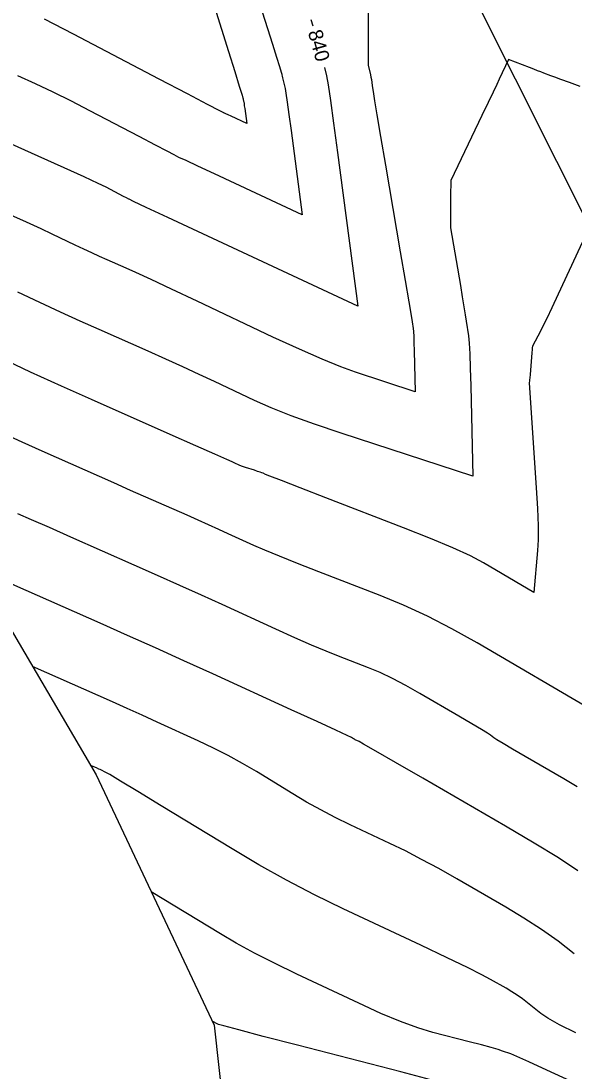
# Model space of a CAD drawing. Extents: x 1715724 to 1716561, y 394063 to 395906.
# Drawn here: x 1716345.4 to 1716399.3, y 394300.9 to 394403.2 of the extents above; entities that cross this region are included whole.
import ezdxf

# ---------------------------------------------------------------- set-up
doc = ezdxf.new("R2010")
doc.units = 0
for name, color, linetype in [('DT_X_Contour_Major', 7, 'Continuous'), ('DT_X_Contour_Minor', 7, 'Continuous'), ('DT_X_TIN_Hull', 7, 'Continuous'), ('GE_P_CL_10', 7, 'Continuous')]:
    doc.layers.add(name, color=color, linetype=linetype)

msp = doc.modelspace()

# ---------------------------------------------------------------- linework, layer by layer
at = {"layer": 'DT_X_Contour_Major'}
for points in [[(1716373.61, 394403.29), (1716373.81, 394402.67)], [(1716374.94, 394398.63), (1716375.13, 394397.81), (1716375.29, 394396.94), (1716375.52, 394395.41), (1716375.83, 394393.21), (1716376.22, 394390.33), (1716378.18, 394375.37), (1716359.66, 394384.02), (1716357.57, 394385), (1716356.32, 394385.58), (1716355.9, 394385.78), (1716355.89, 394385.78), (1716355.65, 394385.91), (1716355.35, 394386.06), (1716354.94, 394386.28), (1716353.66, 394386.95), (1716352.89, 394387.33), (1716351.53, 394387.96), (1716349.59, 394388.85), (1716347.05, 394389.99), (1716339.51, 394393.37)], [(1716399.56, 394328.56), (1716398.27, 394329.33), (1716394.51, 394331.49), (1716393.27, 394332.22), (1716392.34, 394332.76), (1716391.74, 394333.13), (1716391.45, 394333.31), (1716391.13, 394333.57), (1716390.84, 394333.76), (1716390.23, 394334.13), (1716389.29, 394334.69), (1716388.03, 394335.43), (1716384.24, 394337.65), (1716382.86, 394338.43), (1716381.56, 394339.11), (1716380.35, 394339.68), (1716379.22, 394340.15), (1716376.31, 394341.27), (1716375.11, 394341.75), (1716373.69, 394342.35), (1716372.06, 394343.07), (1716370.2, 394343.91), (1716364.96, 394346.31), (1716362.95, 394347.22), (1716360.86, 394348.16), (1716358.68, 394349.14), (1716356.41, 394350.14), (1716350.24, 394352.87), (1716348.13, 394353.8), (1716346.4, 394354.56), (1716345.06, 394355.15)], [(1716388.29, 394299.2), (1716385.79, 394299.87), (1716382.38, 394300.77), (1716372.3, 394303.38), (1716368.98, 394304.24), (1716366.59, 394304.87), (1716365.13, 394305.25), (1716364.6, 394305.4), (1716364.42, 394305.49), (1716364.35, 394305.52), (1716364.3, 394305.55), (1716364.24, 394305.58), (1716363.99, 394305.73)]]:
    msp.add_lwpolyline(points, dxfattribs=at)
at = {"layer": 'DT_X_Contour_Minor'}
for points in [[(1716363.69, 394406.22), (1716365.58, 394400.19), (1716366.2, 394398.22), (1716366.64, 394396.8), (1716366.91, 394395.94), (1716367, 394395.65), (1716367, 394395.62), (1716367.01, 394395.6), (1716367.01, 394395.57), (1716367.02, 394395.54), (1716367.03, 394395.49), (1716367.06, 394395.35), (1716367.08, 394395.27), (1716367.1, 394395.12), (1716367.13, 394394.9), (1716367.17, 394394.62), (1716367.36, 394393.16), (1716365.84, 394393.87), (1716365.55, 394394.01), (1716365.34, 394394.1), (1716365.21, 394394.16), (1716365.16, 394394.19), (1716365.13, 394394.2), (1716364.73, 394394.41), (1716363.55, 394395.03), (1716361.58, 394396.05), (1716358.84, 394397.49), (1716350.48, 394401.87), (1716347.66, 394403.33)], [(1716368.65, 394404.75), (1716369.86, 394400.89), (1716370.26, 394399.62), (1716370.55, 394398.71), (1716370.72, 394398.16), (1716370.78, 394397.97), (1716370.78, 394397.95), (1716370.79, 394397.91), (1716370.81, 394397.79), (1716370.86, 394397.61), (1716370.92, 394397.35), (1716371.1, 394396.58), (1716371.18, 394396.11), (1716371.31, 394395.26), (1716371.48, 394394.05), (1716371.69, 394392.48), (1716372.77, 394384.26), (1716364.21, 394388.26), (1716362.6, 394389.01), (1716361.46, 394389.55), (1716360.76, 394389.87), (1716360.53, 394389.98), (1716360.51, 394389.99), (1716360.28, 394390.11), (1716359.6, 394390.47), (1716358.47, 394391.06), (1716356.89, 394391.89), (1716352.07, 394394.41), (1716350.28, 394395.33), (1716348.51, 394396.21), (1716346.77, 394397.04), (1716345.05, 394397.82)], [(1716379.19, 394403.94), (1716379.2, 394401.65), (1716379.2, 394401.19), (1716379.2, 394400.78), (1716379.21, 394400.13), (1716379.21, 394398.85), (1716379.43, 394397.9), (1716379.47, 394397.69), (1716379.52, 394397.44), (1716379.56, 394397.17), (1716379.6, 394396.88), (1716379.71, 394396.05), (1716379.81, 394395.39), (1716380.04, 394394.01), (1716380.4, 394391.91), (1716380.88, 394389.11), (1716382.32, 394380.67), (1716382.8, 394377.87), (1716383.15, 394375.81), (1716383.38, 394374.47), (1716383.48, 394373.86), (1716383.57, 394373.21), (1716383.6, 394372.89), (1716383.63, 394372.42), (1716383.66, 394371.79), (1716383.68, 394371.02), (1716383.77, 394367.03), (1716377.96, 394368.93), (1716376.52, 394369.45), (1716374.7, 394370.2), (1716372.5, 394371.17), (1716369.92, 394372.36), (1716362.54, 394375.85), (1716360.03, 394377.03), (1716358.04, 394377.96), (1716356.56, 394378.65), (1716355.61, 394379.08), (1716353.75, 394379.9), (1716353.03, 394380.22), (1716352.28, 394380.57), (1716351.49, 394380.94), (1716350.66, 394381.33), (1716348.39, 394382.4), (1716347.35, 394382.89), (1716345.91, 394383.55), (1716344.08, 394384.38)], [(1716399.85, 394396.78), (1716398.8, 394397.16), (1716397.97, 394397.46), (1716397.37, 394397.68), (1716397, 394397.82), (1716396.31, 394398.08), (1716396.02, 394398.19), (1716395.7, 394398.31), (1716395.33, 394398.45), (1716394.91, 394398.61), (1716392.87, 394399.39), (1716391.97, 394397.5), (1716391.72, 394396.97), (1716391.36, 394396.21), (1716390.88, 394395.2), (1716390.28, 394393.96), (1716387.24, 394387.61), (1716387.23, 394386.07), (1716387.22, 394385.74), (1716387.22, 394385.4), (1716387.22, 394385.05), (1716387.22, 394384.69), (1716387.22, 394383.01), (1716388.18, 394377.39), (1716388.37, 394376.27), (1716388.53, 394375.31), (1716388.66, 394374.52), (1716388.75, 394373.9), (1716388.96, 394372.47), (1716389.03, 394371.76), (1716389.1, 394370.72), (1716389.15, 394369.34), (1716389.2, 394367.62), (1716389.4, 394358.81), (1716376.55, 394363.01), (1716373.96, 394363.88), (1716371.69, 394364.7), (1716369.74, 394365.47), (1716368.12, 394366.19), (1716364.23, 394368.02), (1716362.73, 394368.72), (1716361.15, 394369.45), (1716359.49, 394370.2), (1716357.75, 394370.98), (1716352.99, 394373.09), (1716351.15, 394373.91), (1716349.22, 394374.79), (1716347.2, 394375.73), (1716345.07, 394376.74)], [(1716400.91, 394383.46), (1716397.7, 394376.55), (1716397.08, 394375.21), (1716396.59, 394374.16), (1716396.22, 394373.41), (1716395.99, 394372.95), (1716395.2, 394371.46), (1716395.2, 394371.4), (1716395.19, 394371.33), (1716395.18, 394371.14), (1716395.15, 394370.84), (1716395.12, 394370.42), (1716395.01, 394369.14), (1716394.98, 394368.72), (1716394.95, 394368.4), (1716394.93, 394368.2), (1716394.92, 394368.1), (1716394.9, 394367.9), (1716395.58, 394357.69), (1716395.69, 394355.67), (1716395.75, 394353.97), (1716395.76, 394352.61), (1716395.71, 394351.57), (1716395.35, 394347.49), (1716390.44, 394350.36), (1716389.17, 394351.04), (1716387.44, 394351.84), (1716385.27, 394352.75), (1716382.65, 394353.79), (1716375.06, 394356.71), (1716372.56, 394357.68), (1716370.75, 394358.38), (1716369.63, 394358.81), (1716369.19, 394358.98), (1716368.95, 394359.09), (1716368.83, 394359.14), (1716368.66, 394359.2), (1716368.42, 394359.28), (1716368.12, 394359.38), (1716367.26, 394359.66), (1716366.96, 394359.76), (1716366.7, 394359.86), (1716366.49, 394359.94), (1716366.32, 394360.01), (1716365.93, 394360.2), (1716365.44, 394360.42), (1716364.27, 394360.94), (1716362.42, 394361.76), (1716359.89, 394362.88), (1716352.23, 394366.28), (1716349.31, 394367.58), (1716346.3, 394368.95), (1716343.21, 394370.39)], [(1716401.34, 394335.82), (1716389.81, 394342.56), (1716387.36, 394343.94), (1716384.98, 394345.17), (1716382.65, 394346.25), (1716380.37, 394347.19), (1716374.38, 394349.5), (1716372.3, 394350.31), (1716370.55, 394351.01), (1716369.13, 394351.6), (1716368.04, 394352.07), (1716365.57, 394353.2), (1716364.63, 394353.63), (1716363.64, 394354.07), (1716362.62, 394354.53), (1716361.55, 394355.01), (1716356.05, 394357.43), (1716354.43, 394358.15), (1716347.43, 394361.26), (1716345.48, 394362.13), (1716343.51, 394363.02)], [(1716399.61, 394320.36), (1716397.73, 394321.62), (1716395.38, 394323.07), (1716392.59, 394324.72), (1716384.52, 394329.38), (1716381.86, 394330.91), (1716379.94, 394332.02), (1716378.75, 394332.7), (1716378.31, 394332.95), (1716378.09, 394333.05), (1716378.01, 394333.09), (1716377.93, 394333.13), (1716377.85, 394333.18), (1716377.78, 394333.22), (1716377.58, 394333.34), (1716377.16, 394333.54), (1716376.04, 394334.06), (1716374.22, 394334.9), (1716371.7, 394336.05), (1716364.07, 394339.54), (1716361.23, 394340.83), (1716358.46, 394342.09), (1716355.74, 394343.3), (1716353.09, 394344.48), (1716340.83, 394349.89)], [(1716399.27, 394312.29), (1716397.7, 394313.5), (1716396.07, 394314.65), (1716394.37, 394315.76), (1716392.61, 394316.82), (1716387.82, 394319.59), (1716386.07, 394320.58), (1716384.4, 394321.48), (1716382.82, 394322.3), (1716381.32, 394323.03), (1716377.43, 394324.86), (1716375.99, 394325.57), (1716374.58, 394326.3), (1716373.2, 394327.06), (1716371.85, 394327.86), (1716368.3, 394330.03), (1716366.95, 394330.82), (1716365.55, 394331.59), (1716364.12, 394332.32), (1716362.64, 394333.02), (1716358.64, 394334.85), (1716357.16, 394335.53), (1716355.71, 394336.18), (1716354.29, 394336.82), (1716352.9, 394337.43), (1716346.48, 394340.26)], [(1716399.43, 394304.57), (1716397.85, 394305.37), (1716396.71, 394306), (1716396.01, 394306.47), (1716394.72, 394307.5), (1716394.23, 394307.88), (1716393.71, 394308.24), (1716393.18, 394308.59), (1716392.63, 394308.92), (1716391.12, 394309.79), (1716390.28, 394310.24), (1716388.86, 394310.95), (1716386.88, 394311.9), (1716384.33, 394313.11), (1716376.77, 394316.67), (1716373.97, 394318.04), (1716371.23, 394319.46), (1716368.55, 394320.95), (1716365.93, 394322.5), (1716359.02, 394326.71), (1716356.74, 394328.1), (1716355.07, 394329.11), (1716354.02, 394329.74), (1716353.58, 394329.99), (1716353.22, 394330.16), (1716353.09, 394330.22), (1716352.96, 394330.28), (1716352.71, 394330.39), (1716352.14, 394330.64)], [(1716398.94, 394299.87), (1716396.6, 394300.96), (1716394.85, 394301.76), (1716393.68, 394302.29), (1716393.09, 394302.53), (1716392.29, 394302.81), (1716391.86, 394302.95), (1716391.17, 394303.14), (1716390.23, 394303.4), (1716389.03, 394303.71), (1716385.49, 394304.63), (1716384.04, 394305.07), (1716382.36, 394305.68), (1716380.44, 394306.48), (1716378.29, 394307.46), (1716372.23, 394310.31), (1716370.07, 394311.36), (1716368.11, 394312.35), (1716366.35, 394313.31), (1716364.8, 394314.21), (1716358.05, 394318.33)]]:
    msp.add_lwpolyline(points, dxfattribs=at)
at = {"layer": 'DT_X_TIN_Hull'}
msp.add_lwpolyline([(1716124.57, 394620.66), (1716148.93, 394620.11), (1716178.47, 394618.57), (1716198.37, 394601.55), (1716214.15, 394581.11), (1716226.91, 394558.69), (1716239.76, 394534.12), (1716254, 394509.73), (1716267.48, 394486.32), (1716281.65, 394460.47), (1716295.06, 394433.01), (1716310.25, 394404.29), (1716324.4, 394380.06), (1716338.75, 394353.43), (1716352.69, 394329.7), (1716364.18, 394305.34), (1716366.88, 394280.88)], dxfattribs=at)
at = {"layer": 'GE_P_CL_10'}
msp.add_line((1716447.81, 394289.08), (1716249.46, 394685.42), dxfattribs=at)

# ---------------------------------------------------------------- texts
at = {"layer": 'DT_X_Contour_Major'}
msp.add_text('840', height=1.4, rotation=285.6277, dxfattribs=at).set_placement((1716373.31, 394402.08))

doc.saveas('drawing.dxf')
